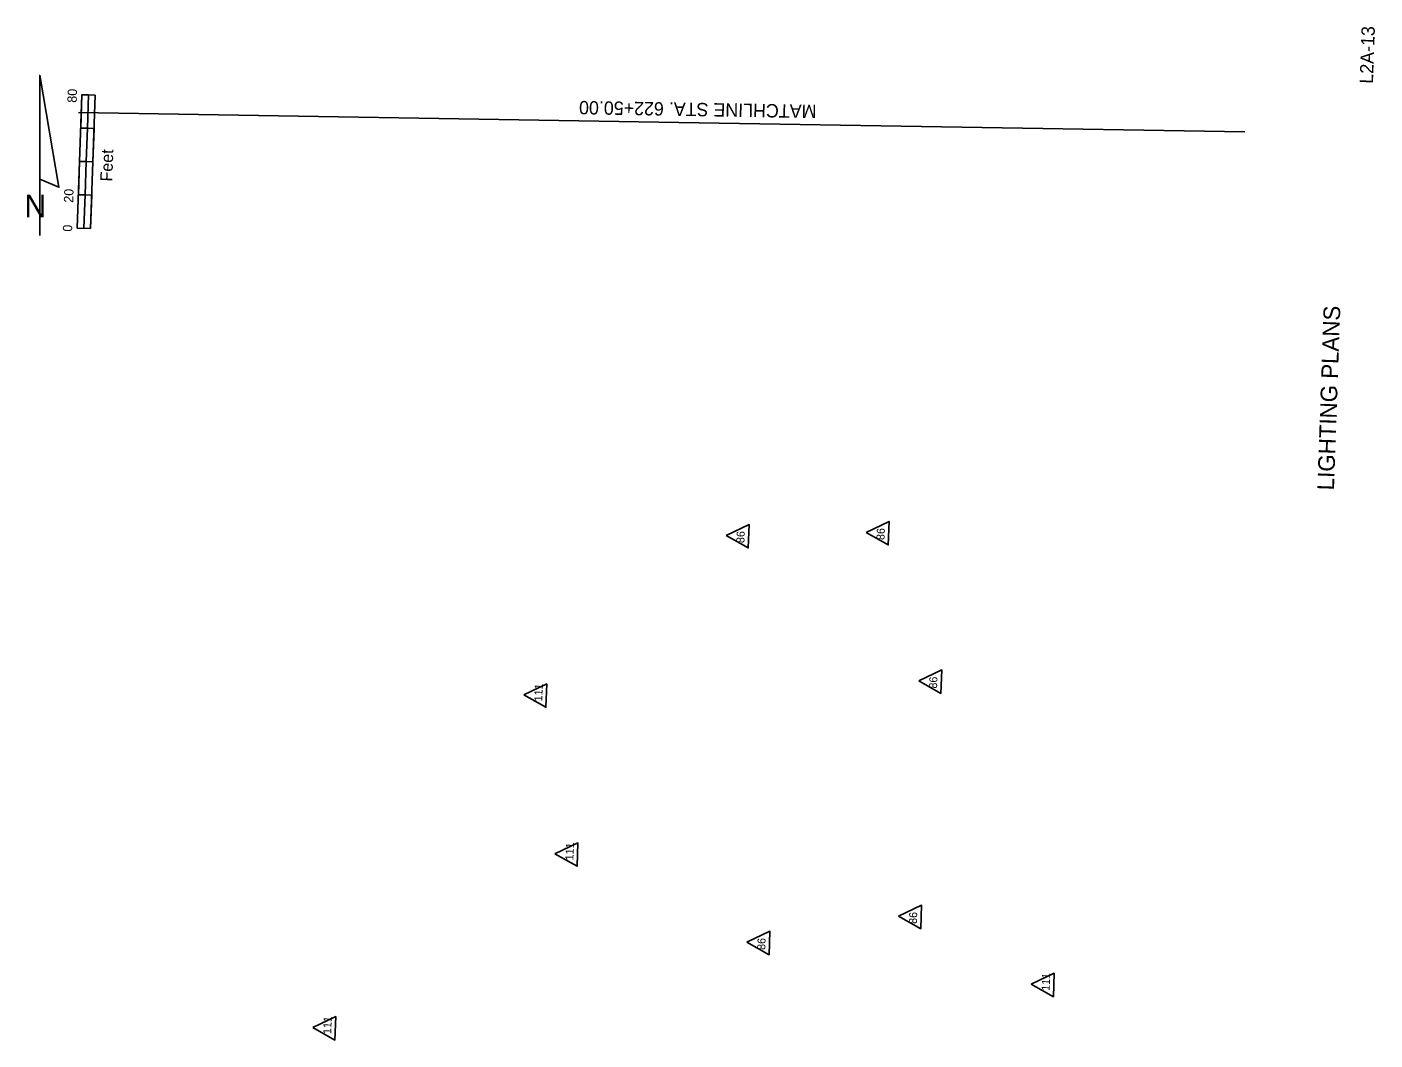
# Model space of a CAD drawing. Extents: x 928669 to 929521, y 636891 to 638153.
# Drawn here: x 928712 to 929521, y 637545 to 638153 of the extents above; entities that cross this region are included whole.
import ezdxf

# ---------------------------------------------------------------- set-up
doc = ezdxf.new("R2010")
doc.units = 0
for name, color, linetype in [('Cloud_dp', 7, 'Continuous'), ('NorthArw_dp', 7, 'Continuous'), ('PlotBorder_dp', 7, 'Continuous'), ('Scale_dp', 7, 'Continuous'), ('ScratchEle_dp', 7, 'Continuous'), ('TextTitle', 7, 'Continuous')]:
    doc.layers.add(name, color=color, linetype=linetype)

msp = doc.modelspace()

# ---------------------------------------------------------------- linework, layer by layer
at = {"layer": 'Cloud_dp'}
for points in [[(929131.74, 637847.81), (929145.05, 637840.3), (929145.54, 637854.37)], [(929215.77, 637849.63), (929229.08, 637842.12), (929229.57, 637856.19)], [(929247.3, 637760.56), (929260.6, 637753.05), (929261.1, 637767.12)], [(929010.47, 637752.24), (929023.78, 637744.73), (929024.28, 637758.81)], [(929029.16, 637656.92), (929042.47, 637649.41), (929042.96, 637663.49)], [(929235.2, 637619.48), (929248.51, 637611.96), (929249, 637626.04)], [(929144.26, 637603.89), (929157.57, 637596.38), (929158.06, 637610.45)], [(929314.8, 637578.72), (929328.11, 637571.21), (929328.6, 637585.29)], [(928883.91, 637552.78), (928897.22, 637545.27), (928897.71, 637559.35)]]:
    msp.add_lwpolyline(points, close=True, dxfattribs=at)
at = {"layer": 'NorthArw_dp'}
msp.add_line((928720.15, 638027.69), (928720.15, 638123.69), dxfattribs=at)
msp.add_lwpolyline([(928720.15, 638061.29), (928720.15, 638123.69), (928731.67, 638056.49)], close=True, dxfattribs=at)
at = {"layer": 'PlotBorder_dp'}
msp.add_lwpolyline([(929442.86, 638089.68), (929103.36, 638095.32), (928743.41, 638101.3)], dxfattribs=at)
at = {"layer": 'Scale_dp'}
for p, q in [((928745.46, 638112.01), (928742.66, 638032.06)), ((928753.45, 638111.73), (928745.46, 638112.01)), ((928750.66, 638031.78), (928753.45, 638111.73)), ((928742.66, 638032.06), (928750.66, 638031.78))]:
    msp.add_line(p, q, dxfattribs=at)
for points in [[(928748.76, 638091.88), (928744.76, 638092.02), (928745.46, 638112.01), (928749.45, 638111.87)], [(928752.05, 638071.75), (928748.06, 638071.89), (928748.76, 638091.88), (928752.75, 638091.74)], [(928747.36, 638051.91), (928743.36, 638052.05), (928744.06, 638072.03), (928748.06, 638071.89)], [(928750.66, 638031.78), (928746.66, 638031.92), (928747.36, 638051.91), (928751.36, 638051.77)]]:
    msp.add_lwpolyline(points, close=True, dxfattribs=at)

# ---------------------------------------------------------------- texts
at = {"layer": 'Cloud_dp'}
for s, p in [('86', (929226.77, 637844.98)), ('86', (929142.74, 637843.16)), ('86', (929258.29, 637755.91)), ('111', (929021.49, 637748.22)), ('111', (929040.18, 637652.9)), ('86', (929246.2, 637614.83)), ('86', (929155.25, 637599.24)), ('111', (929325.82, 637574.7)), ('111', (928894.93, 637548.76))]:
    msp.add_text(s, height=4.8, rotation=87.99782, dxfattribs=at).set_placement(p)
at = {"layer": 'NorthArw_dp'}
msp.add_text('N', height=13.43, dxfattribs=at).set_placement((928711.03, 638038.56))
at = {"layer": 'PlotBorder_dp'}
msp.add_text('MATCHLINE STA. 622+50.00', height=8, rotation=179.04782, dxfattribs=at).set_placement((929186.06, 638105.95))
at = {"layer": 'Scale_dp'}
for s, height, p in [('80', 5.6, (928742.28, 638107.13)), ('Feet', 7.2, (928763.65, 638059.88)), ('20', 5.6, (928740.19, 638047.19)), ('0', 5.6, (928739.58, 638029.83))]:
    msp.add_text(s, height=height, rotation=87.99782, dxfattribs=at).set_placement(p)
at = {"layer": 'ScratchEle_dp'}
msp.add_text('        LIGHTING PLANS         ', height=10, rotation=87.99782, dxfattribs=at).set_placement((929495.3, 637845.01))
at = {"layer": 'TextTitle'}
msp.add_text('L2A-13', height=8, rotation=87.99782, dxfattribs=at).set_placement((929519.72, 638118.51))

doc.saveas('drawing.dxf')
